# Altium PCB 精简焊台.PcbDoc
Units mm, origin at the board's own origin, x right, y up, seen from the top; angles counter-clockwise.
Board outline 70 x 50.01 mm, 2 copper layers (Top Layer, Bottom Layer), stack 0.325 mm thick; 94 components, 71 nets, 283 pads, 209 vias.
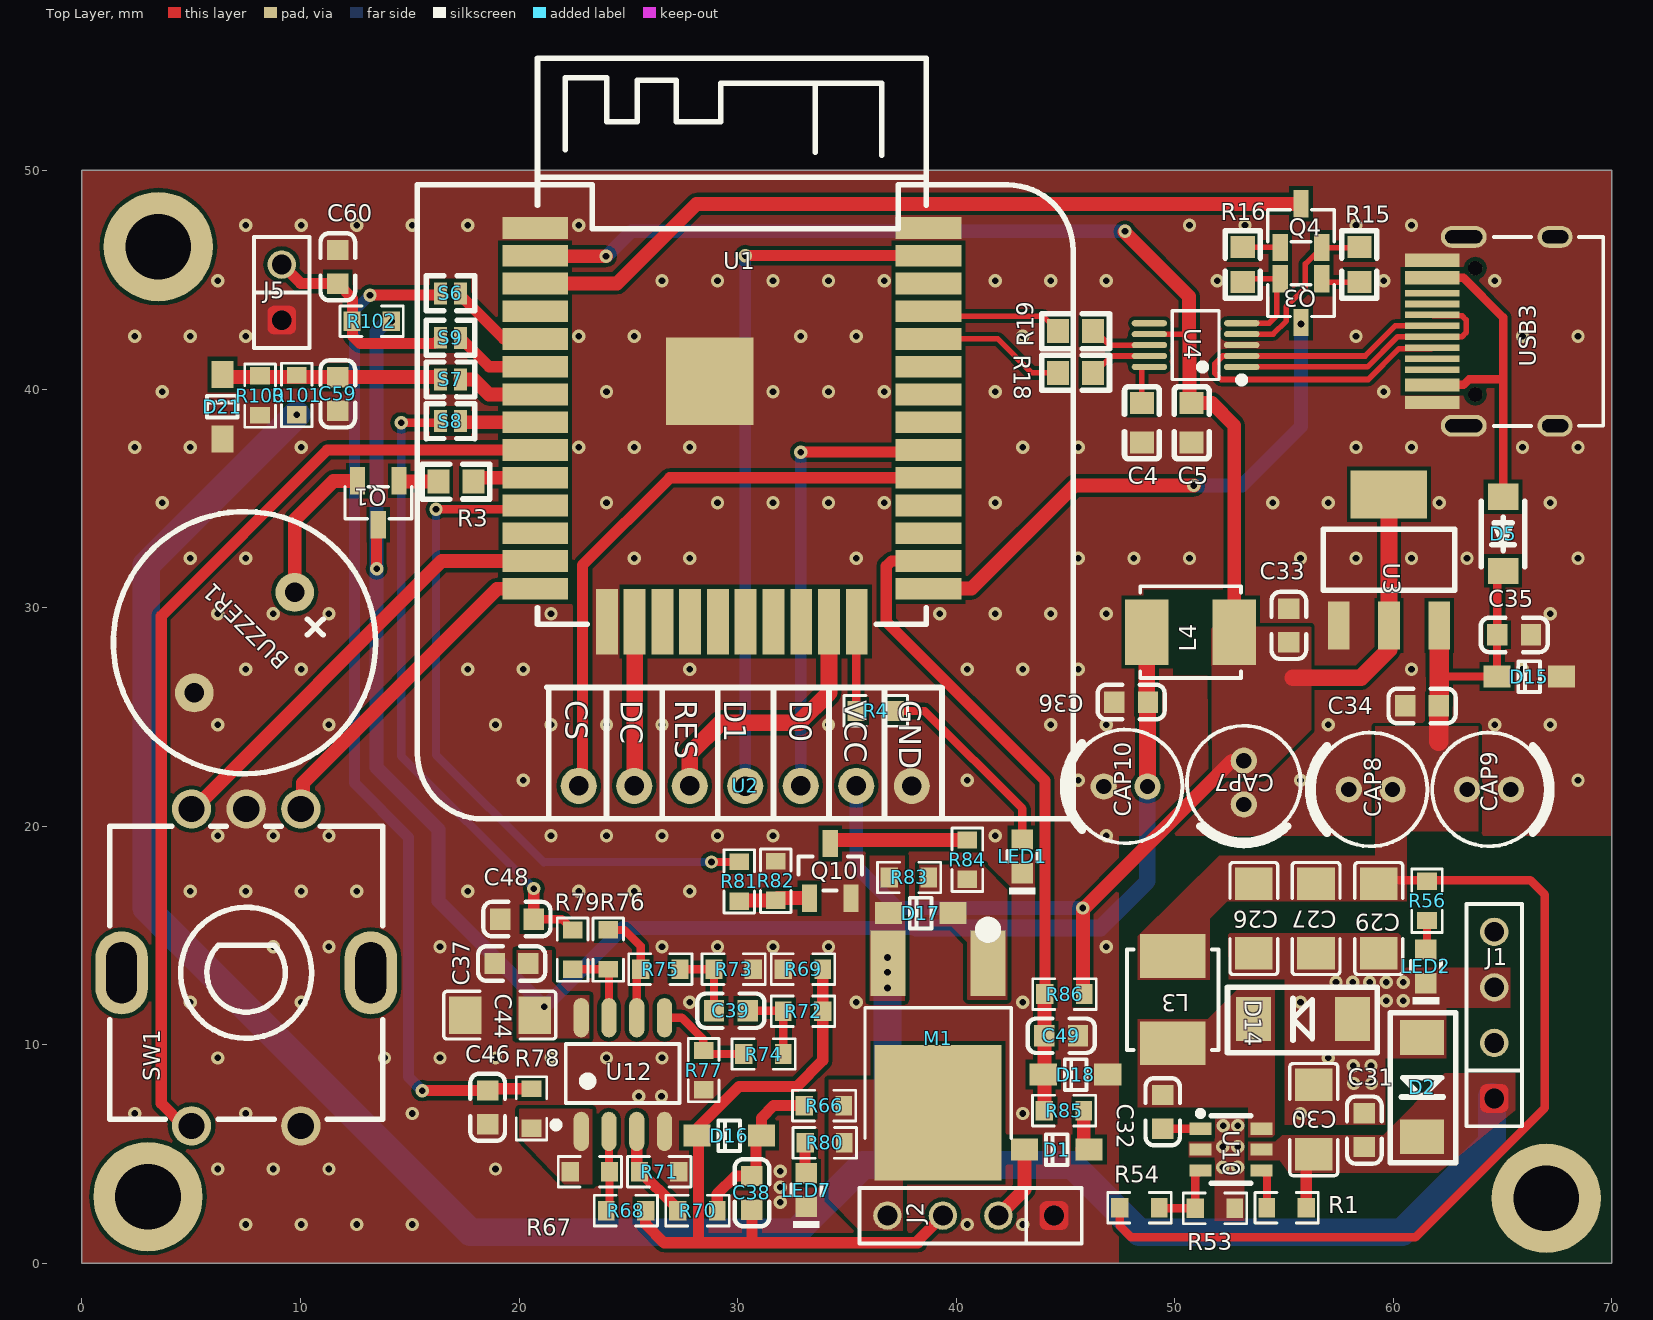
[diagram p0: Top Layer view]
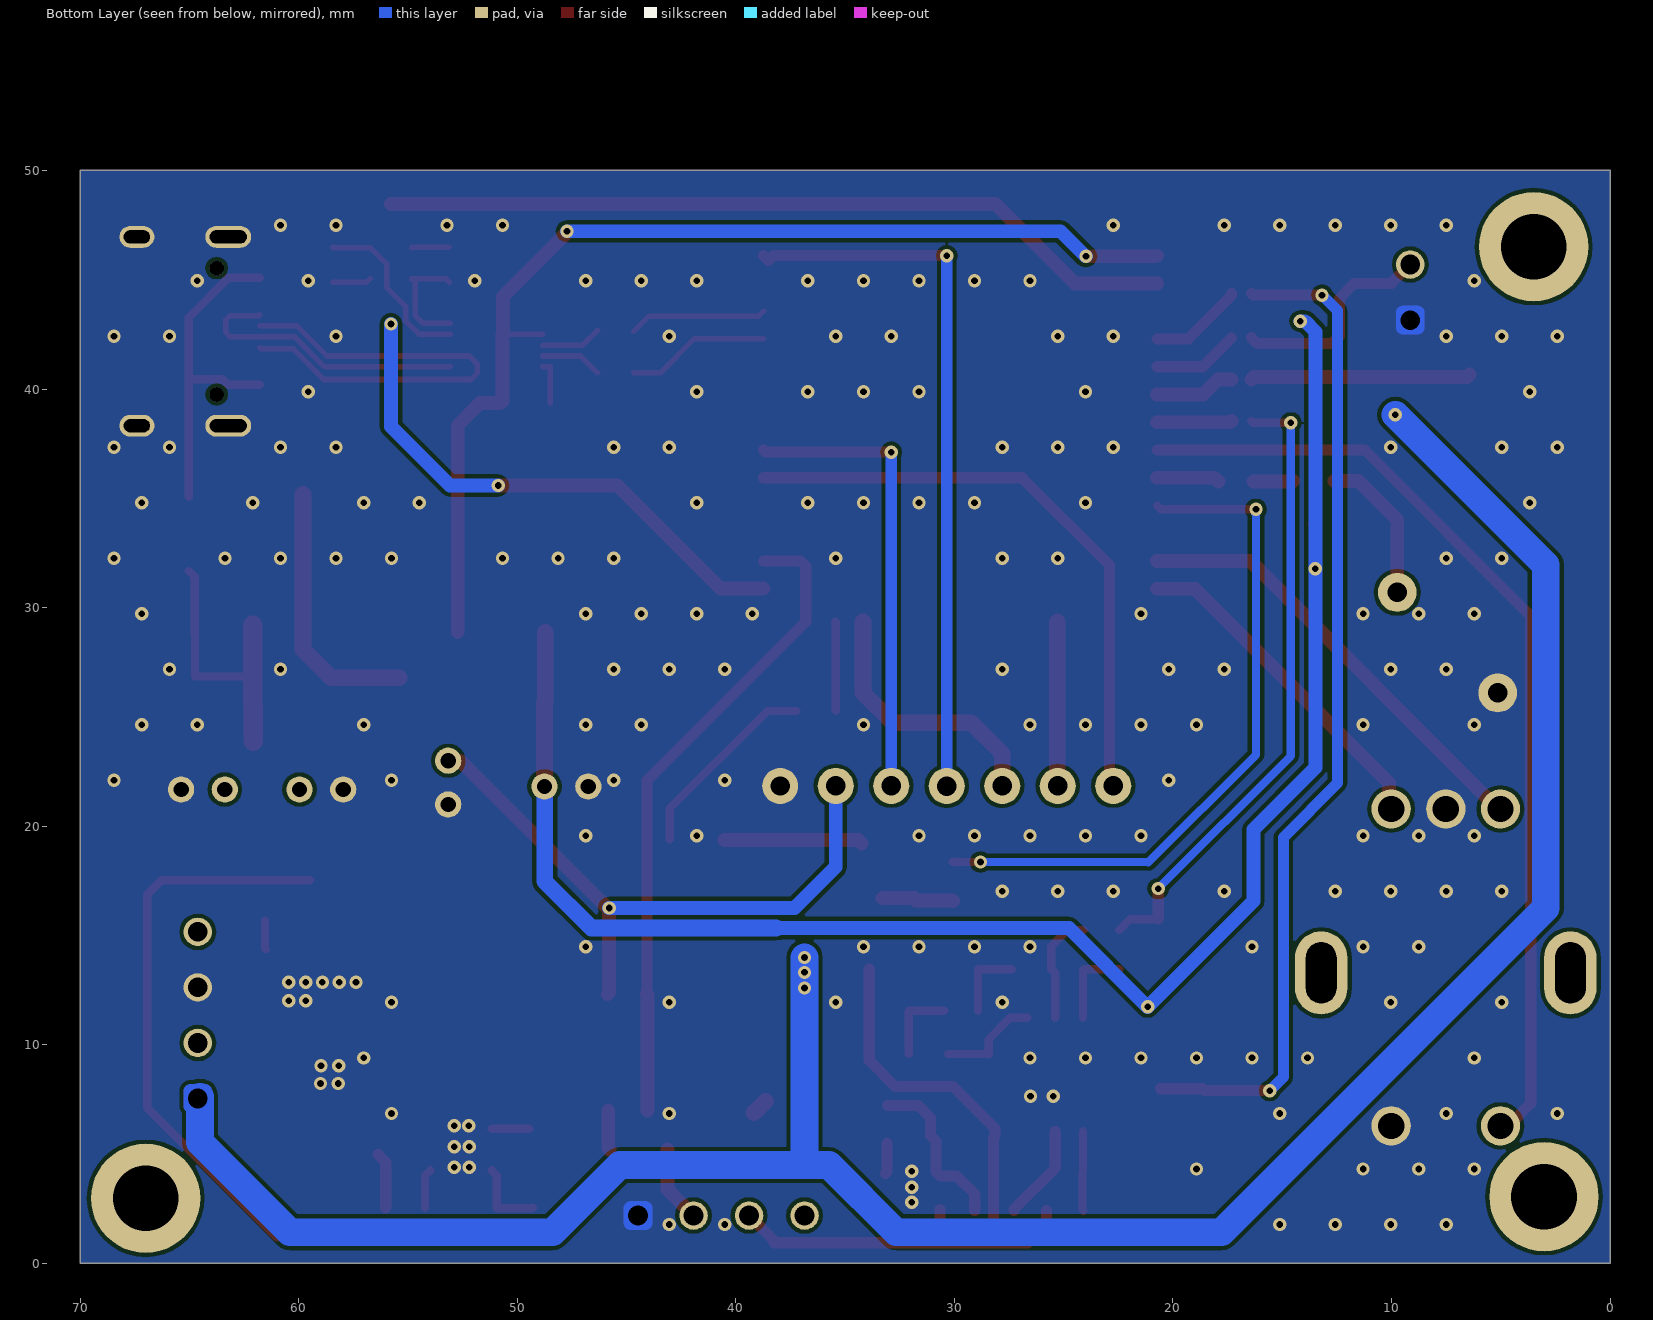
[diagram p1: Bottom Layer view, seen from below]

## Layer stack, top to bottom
Top Solder: solder mask 0.0102, Solder Resist, Dk 3.5
Top Layer: signal copper 0.0356
Dielectric 1: core 0.254, FR-4, Dk 4.2
Bottom Layer: signal copper 0.0356
Bottom Solder: solder mask 0.0102, Solder Resist, Dk 3.5

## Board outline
0,0 0,50.013 70.002,50.013 70.002,0

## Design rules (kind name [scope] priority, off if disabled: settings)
Clearance [All] p1: gap=0.178 ignorepadtopadclearanceinfootprint=FALSE
PolygonConnect PolygonConnect_2 [All] p1: connectstyle=Direct reliefconductorwidth=0.254 reliefentries=4 polygonreliefangle="90 Angle" airgapwidth=0.254
PolygonConnect PolygonConnect_1 [IsVia] p2: connectstyle=Direct reliefconductorwidth=0.254 reliefentries=4 polygonreliefangle="90 Angle" airgapwidth=0.254
PolygonConnect [All] p3: connectstyle=Relief reliefconductorwidth=0.254 reliefentries=4 polygonreliefangle="90 Angle" airgapwidth=0.254
RoutingVias [All] p1: holewidth=0.711 width=1.27 viastyle="Through Hole" minholewidth=0.711 minwidth=1.27 maxholewidth=0.711 maxwidth=1.27
SolderMaskExpansion [All] p1: expansion=0.064
Width Width_1 [InNetClass('New Class')] p1: maxlimit=2.54 minlimit=0.254 preferedwidth=0.508
Width [All] p2: maxlimit=2.54 minlimit=0.254 preferedwidth=0.254
30 further rules are at their usual default settings.

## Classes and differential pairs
net class "New Class": 5V AVCC DVCC NetD17_1 NetJ2_4 VBUS VIN

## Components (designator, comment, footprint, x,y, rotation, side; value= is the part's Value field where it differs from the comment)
BUZZER1 "GMC1205YA-16R2048" BUZ-TH_BD12.0-P6.50-D0.6-FD 7.442,28.397 r45 top
C4 "1u" C0603 48.501,38.456 r270 top
C5 "10u" C0603 50.775,38.456 r90 top
C26 "10uF" 电容 53.848,15.875 r270 top
C27 "10uF" 电容 56.694,15.875 r270 top
C29 "0.1uF" 电容 59.563,15.875 r270 top
C30 "4.7uF" 电容 56.134,6.477 r90 top
C31 "0.1uF" 0603C 58.674,6.096 r90 top
C32 "0.1uF" 0603C 49.454,6.934 r270 top
C33 "0.1uF" 0603C 55.22,29.185 r270 top
C34 "0.1uF" 0603C 61.316,25.502 r0 top
C35 "0.1uF" 0603C 65.532,28.753 r0 top
C36 "0.1uF" 0603C 48.006,25.679 r0 top
C37 "0.1uF" 0603C 19.66,13.716 r0 top
C38 "0.1uF" 0603C 30.658,3.226 r270 top
C39 "0.1uF" 0603C 29.693,11.557 r180 top
C44 "4.7uF" 电容 19.025,11.582 r0 top
C46 "10nF" 0603C 18.567,7.137 r270 top
C48 "10nF" 0603C 19.906,15.748 r180 top
C49 "0.1uF" 0603C 44.806,10.414 r180 top
C59 "1uF" 0603C 11.709,39.776 r270 top
C60 "1uF" 0603C 11.709,45.593 r90 top
CAP7 "22uF" CAPX-5.0 53.162,21.996 r90 top
CAP8 "22uF" CAPX-5.0 58.963,21.679 r0 top
CAP9 "100uF" CAPX-5.0 64.38,21.679 r180 top
CAP10 "22uF" CAPX-5.0 47.752,21.819 r0 top
D1 "1N4148" LC-SOD-123 44.602,5.207 r0 top
D2 "TVS" "二极管 SMA(DO-214AC)" 61.316,10.123 r270 top
D5 "1N5819HW-7-F" SOD-123_L2.8-W1.8-LS3.7-FD 65.024,33.376 r270 top
D14 "B5819" "二极管 SMA(DO-214AC)" 57.926,11.176 r180 top
D15 "SMA6.0A" LC-SOD-123 66.218,26.848 r0 top
D16 "1N4148" LC-SOD-123 29.616,5.842 r0 top
D17 "ZMM12" LC-SOD-123 38.379,16.027 r0 top
D18 "SMF3.3A" LC-SOD-123 45.466,8.636 r0 top
D21 "SMF3.3A" LC-SOD-123 6.426,39.192 r270 top
J1 "CONN4" SIP-4 64.618,7.544 r90 top
J2 "CONN4" SIP-4 44.475,2.184 r180 top
J5 "NTC 10K" SIP-2 9.144,43.155 r90 top
L3 "22uH" LIN0520 49.911,12.065 r90 top
L4 "22uH" LIN0520 50.724,28.88 r180 top
LED1 "LED" LC-0603-LED 43.028,18.618 r270 top
LED2 "LED" LC-0603-LED 61.493,13.589 r270 top
LED7 "LED" LC-0603-LED 33.147,3.353 r270 top
M1 "MOS-ASM6115" MOS-ASM6115 39.802,9.5 r90 top
Q1 "S8050" SOT-23-3_L2.9-W1.3-P1.90-LS2.4-BR 13.564,34.798 r90 top
Q3 "S8050" SOT-23-3_L2.9-W1.3-P1.90-LS2.4-BR 55.778,44.044 r90 top
Q4 "S8050" SOT-23-3_L2.9-W1.3-P1.90-LS2.4-BR 55.778,47.473 r270 top
Q10 "S8050" LC-SOT-23(SOT-23-3) 34.239,17.958 r270 top
R1 "100K" 0603R 55.118,2.54 r0 top
R3 "10k" R0603 17.12,35.763 r0 top
R4 "2K" 0603R 36.322,25.273 r180 top
R15 "10k" R0603 58.445,45.695 r90 top
R16 "10k" R0603 53.111,45.695 r270 top
R18 "220R" R0603 45.466,40.742 r180 top
R19 "220R" R0603 45.466,42.647 r180 top
R53 "18K" 0603R 51.841,2.515 r180 top
R54 "100K" 0603R 48.387,2.54 r180 top
R56 "3K" 0603R 61.544,16.586 r90 top
R66 "10K" 0603R 33.96,7.214 r180 top
R67 "200K" 0603R 23.241,4.191 r180 top
R68 "2K" 0603R 24.892,2.413 r0 top
R69 "0.02R" 0603R 32.995,13.462 r180 top
R70 "2K" 0603R 28.169,2.413 r180 top
R71 "200K" 0603R 26.416,4.191 r0 top
R72 "10R" 0603R 32.995,11.532 r0 top
R73 "10R" 0603R 29.82,13.462 r0 top
R74 "1K" 0603R 31.191,9.576 r180 top
R75 "1K" 0603R 26.467,13.462 r180 top
R76 "20K" 0603R 24.079,14.351 r90 top
R77 "20K" 0603R 28.448,8.839 r270 top
R78 "1K" 0603R 20.574,7.087 r270 top
R79 "10K" 0603R 22.454,14.351 r270 top
R80 "10K" 0603R 33.985,5.512 r180 top
R81 "1K" 0603R 30.074,17.475 r270 top
R82 "51K" 0603R 31.75,17.501 r270 top
R83 "10K" 0603R 37.846,17.653 r180 top
R84 "2K" 0603R 40.513,18.466 r270 top
R85 "1K" 0603R 44.938,6.985 r180 top
R86 "10K" 0603R 44.958,12.319 r180 top
R100 "1K" 0603R 8.153,39.7 r90 top
R101 "10K" 0603R 9.83,39.726 r270 top
R102 "10K" 0603R 13.259,43.104 r0 top
S6 "Solder" SW_HAND_WELD_JX 16.866,44.374 r180 top
S7 "Solder" SW_HAND_WELD_JX 16.866,40.437 r180 top
S8 "Solder" SW_HAND_WELD_JX 16.866,38.534 r180 top
S9 "Solder" SW_HAND_WELD_JX 16.866,42.342 r180 top
SW1 "Rotary Enc" SW-TH_PEC11R-4XXXF-SXXXX 7.518,13.538 r0 top
U1 "ESP32-S" WIRELM-SMD_ESP32-S 29.735,38.366 r0 top
U2 "0.96OLED" "OLED 12864 SPI 7P" 30.352,21.84 r0 top
U3 "AMS1117" "LDO线性稳压 (SOT-223)" 59.803,32.185 r270 top
U4 "CH340E" MSOP-10_L3.0-W3.0-P0.50-LS5.0-BL 50.952,42.012 r90 top
U10 "LMR16006" "开关电源 (LMR16006)" 52.959,5.334 r270 top
U12 "GS8552" LC-SOP-8-150MIL 24.74,8.636 r0 top
USB3 "USB-TYPEC-16P" USB-TYPE-C-16P 67.404,38.321 r90 top

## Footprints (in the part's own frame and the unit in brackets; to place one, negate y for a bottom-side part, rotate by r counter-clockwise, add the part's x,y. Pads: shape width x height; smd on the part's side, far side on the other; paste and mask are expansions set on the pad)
0603C [mm]
  rect 0.93x0.98 smd: 1(-0.77,0) 2(0.77,0)
  silkscreen extent -1.53,-0.79 1.54,0.79, body extent -0.8,-0.4 0.8,0.4, height 0.3
0603R [mm]
  rect 0.762x0.9 smd: 1(-0.9,0)
  rect 0.8x0.9 smd: 2(0.9,0)
  silkscreen extent -1.45,-0.7 1.45,0.7, body extent -0.85,-0.4 0.85,0.4, height 0.56
BUZ-TH_BD12.0-P6.50-D0.6-FD [mil]
  round 70 hole 35.4: 1(128,0) 2(-128,0)
  silkscreen extent -236,-236 236,236
C0603 [mm]
  rect 1x1.1 smd: 1(-0.9,0) 2(0.9,0)
  silkscreen extent -1.65,-0.8 1.65,0.8
CAPX-5.0 [mm]
  round 1.2 hole 0.7: 1(1,0) 2(-1,0)
  silkscreen extent -2.83,-2.6 2.6,2.6
LC-0603-LED [mm]
  rect 0.93x0.98 smd: A(-0.77,0) K(0.77,0)
  silkscreen extent -0.25,-0.69 1.72,0.69
LC-SOD-123 [mm]
  rect 1.25x1 smd: 1(1.475,0) 2(-1.475,0)
  silkscreen extent -0.5,-0.7 0.5,0.7
LC-SOP-8-150MIL [mm]
  oval 0.7x1.8 smd: 1(-1.893,-2.6) 2(-0.623,-2.6) 3(0.647,-2.6) 4(1.917,-2.6) 5(1.917,2.6) 6(0.647,2.6) 7(-0.623,2.6) 8(-1.893,2.6)
  silkscreen extent -3.2,-2.45 2.6,1.4
LC-SOT-23(SOT-23-3) [mm]
  rect 1.25x0.7 smd: 1(1.25,-0.95) 2(1.25,0.95) 3(-1.25,0)
  silkscreen extent -0.65,-1.46 0.9,1.46
"LDO线性稳压 (SOT-223)" [mm]
  rect 2.2x1 smd: 1(3,-2.3) 2(3,0) 3(3,2.3)
  rect 2.2x3.5 smd: 2(-3,0)
  silkscreen extent -1.4,-3 1.4,3, body extent -3.49,-3.24 3.49,3.24, height 1.64
LIN0520 [mm]
  rect 2x3 smd: 1(-2,0) 2(2,0)
  silkscreen extent -2.3,-2.1 2.3,2.1
MOS-ASM6115 [mm]
  rect 3x1.6 smd: 1(4.233,-1.662) 3(4.233,2.918)
  rect 6.2x5.8 smd: 2(-2.615,0.628)
  silkscreen extent -3.78,-2.72 6.06,3.97
MSOP-10_L3.0-W3.0-P0.50-LS5.0-BL [mm]
  oval 0.28x1.62 smd: 1(-1,-2.11) 2(-0.5,-2.11) 3(0,-2.11) 4(0.5,-2.11) 5(1,-2.11) 6(1,2.11) 7(0.5,2.11) 8(0,2.11) 9(-0.5,2.11) 10(-1,2.11)
  silkscreen extent -1.74,-2.26 1.58,1.07
"OLED 12864 SPI 7P" [mm]
  round 1.65 hole 0.89: 1(7.619,-0.001) 2(5.079,0.004) 3(2.539,0.004) 4(-0.001,-0.004) 5(-2.539,0.001) 6(-5.079,0.001) 7(-7.619,0.004)
  silkscreen extent -15,-1.5 15,27.5
R0603 [mm]
  rect 1x1.1 smd: 1(-0.8,0) 2(0.8,0)
  silkscreen extent -1.55,-0.8 1.55,0.81
SIP-2 [mm]
  round 0 hole 0.9: 1(0,0)
  round 1.3 hole 0.9: 2(2.54,0)
  Top Layer region: -0.65,0.325 -0.649,0.349 -0.646,0.373 -0.642,0.397 -0.636,0.421 -0.628,0.444 -0.618,0.466 -0.606,0.488 -0.594,0.508 -0.579,0.528 -0.563,0.546 -0.546,0.563 -0.528,0.579 -0.508,0.594 -0.488,0.606 -0.466,0.618 -0.444,0.628 -0.421,0.636 -0.397,0.642 -0.373,0.646 -0.349,0.649 -0.325,0.65 0.325,0.65 0.349,0.649 0.373,0.646 0.397,0.642 0.421,0.636 0.444,0.628 0.466,0.618 0.488,0.606 0.508,0.594 0.528,0.579 0.546,0.563 0.563,0.546 0.579,0.528 0.594,0.508 0.606,0.488 0.618,0.466 0.628,0.444 0.636,0.421 0.642,0.397 0.646,0.373 0.649,0.349 0.65,0.325 0.65,-0.325 0.649,-0.349 0.646,-0.373 0.642,-0.397 0.636,-0.421 0.628,-0.444 0.618,-0.466 0.606,-0.488 0.594,-0.508 0.579,-0.528 0.563,-0.546 0.546,-0.563 0.528,-0.579 0.508,-0.594 0.488,-0.606 0.466,-0.618 0.444,-0.628 0.421,-0.636 0.397,-0.642 0.373,-0.646 0.349,-0.649 0.325,-0.65 -0.325,-0.65 -0.349,-0.649 -0.373,-0.646 -0.397,-0.642 -0.421,-0.636 -0.444,-0.628 -0.466,-0.618 -0.488,-0.606 -0.508,-0.594 -0.528,-0.579 -0.546,-0.563 -0.563,-0.546 -0.579,-0.528 -0.594,-0.508 -0.606,-0.488 -0.618,-0.466 -0.628,-0.444 -0.636,-0.421 -0.642,-0.397 -0.646,-0.373 -0.649,-0.349 -0.65,-0.325
  Bottom Layer region: -0.65,0.325 -0.649,0.349 -0.646,0.373 -0.642,0.397 -0.636,0.421 -0.628,0.444 -0.618,0.466 -0.606,0.488 -0.594,0.508 -0.579,0.528 -0.563,0.546 -0.546,0.563 -0.528,0.579 -0.508,0.594 -0.488,0.606 -0.466,0.618 -0.444,0.628 -0.421,0.636 -0.397,0.642 -0.373,0.646 -0.349,0.649 -0.325,0.65 0.325,0.65 0.349,0.649 0.373,0.646 0.397,0.642 0.421,0.636 0.444,0.628 0.466,0.618 0.488,0.606 0.508,0.594 0.528,0.579 0.546,0.563 0.563,0.546 0.579,0.528 0.594,0.508 0.606,0.488 0.618,0.466 0.628,0.444 0.636,0.421 0.642,0.397 0.646,0.373 0.649,0.349 0.65,0.325 0.65,-0.325 0.649,-0.349 0.646,-0.373 0.642,-0.397 0.636,-0.421 0.628,-0.444 0.618,-0.466 0.606,-0.488 0.594,-0.508 0.579,-0.528 0.563,-0.546 0.546,-0.563 0.528,-0.579 0.508,-0.594 0.488,-0.606 0.466,-0.618 0.444,-0.628 0.421,-0.636 0.397,-0.642 0.373,-0.646 0.349,-0.649 0.325,-0.65 -0.325,-0.65 -0.349,-0.649 -0.373,-0.646 -0.397,-0.642 -0.421,-0.636 -0.444,-0.628 -0.466,-0.618 -0.488,-0.606 -0.508,-0.594 -0.528,-0.579 -0.546,-0.563 -0.563,-0.546 -0.579,-0.528 -0.594,-0.508 -0.606,-0.488 -0.618,-0.466 -0.628,-0.444 -0.636,-0.421 -0.642,-0.397 -0.646,-0.373 -0.649,-0.349 -0.65,-0.325
  silkscreen extent -1.27,-1.27 3.81,1.27
SIP-4 [mm]
  round 0 hole 0.9: 1(0,0)
  round 1.3 hole 0.9: 2(2.54,0) 3(5.08,0) 4(7.62,0)
  Top Layer region: -0.65,0.325 -0.649,0.349 -0.646,0.373 -0.642,0.397 -0.636,0.421 -0.628,0.444 -0.618,0.466 -0.606,0.488 -0.594,0.508 -0.579,0.528 -0.563,0.546 -0.546,0.563 -0.528,0.579 -0.508,0.594 -0.488,0.606 -0.466,0.618 -0.444,0.628 -0.421,0.636 -0.397,0.642 -0.373,0.646 -0.349,0.649 -0.325,0.65 0.325,0.65 0.349,0.649 0.373,0.646 0.397,0.642 0.421,0.636 0.444,0.628 0.466,0.618 0.488,0.606 0.508,0.594 0.528,0.579 0.546,0.563 0.563,0.546 0.579,0.528 0.594,0.508 0.606,0.488 0.618,0.466 0.628,0.444 0.636,0.421 0.642,0.397 0.646,0.373 0.649,0.349 0.65,0.325 0.65,-0.325 0.649,-0.349 0.646,-0.373 0.642,-0.397 0.636,-0.421 0.628,-0.444 0.618,-0.466 0.606,-0.488 0.594,-0.508 0.579,-0.528 0.563,-0.546 0.546,-0.563 0.528,-0.579 0.508,-0.594 0.488,-0.606 0.466,-0.618 0.444,-0.628 0.421,-0.636 0.397,-0.642 0.373,-0.646 0.349,-0.649 0.325,-0.65 -0.325,-0.65 -0.349,-0.649 -0.373,-0.646 -0.397,-0.642 -0.421,-0.636 -0.444,-0.628 -0.466,-0.618 -0.488,-0.606 -0.508,-0.594 -0.528,-0.579 -0.546,-0.563 -0.563,-0.546 -0.579,-0.528 -0.594,-0.508 -0.606,-0.488 -0.618,-0.466 -0.628,-0.444 -0.636,-0.421 -0.642,-0.397 -0.646,-0.373 -0.649,-0.349 -0.65,-0.325
  Bottom Layer region: -0.65,0.325 -0.649,0.349 -0.646,0.373 -0.642,0.397 -0.636,0.421 -0.628,0.444 -0.618,0.466 -0.606,0.488 -0.594,0.508 -0.579,0.528 -0.563,0.546 -0.546,0.563 -0.528,0.579 -0.508,0.594 -0.488,0.606 -0.466,0.618 -0.444,0.628 -0.421,0.636 -0.397,0.642 -0.373,0.646 -0.349,0.649 -0.325,0.65 0.325,0.65 0.349,0.649 0.373,0.646 0.397,0.642 0.421,0.636 0.444,0.628 0.466,0.618 0.488,0.606 0.508,0.594 0.528,0.579 0.546,0.563 0.563,0.546 0.579,0.528 0.594,0.508 0.606,0.488 0.618,0.466 0.628,0.444 0.636,0.421 0.642,0.397 0.646,0.373 0.649,0.349 0.65,0.325 0.65,-0.325 0.649,-0.349 0.646,-0.373 0.642,-0.397 0.636,-0.421 0.628,-0.444 0.618,-0.466 0.606,-0.488 0.594,-0.508 0.579,-0.528 0.563,-0.546 0.546,-0.563 0.528,-0.579 0.508,-0.594 0.488,-0.606 0.466,-0.618 0.444,-0.628 0.421,-0.636 0.397,-0.642 0.373,-0.646 0.349,-0.649 0.325,-0.65 -0.325,-0.65 -0.349,-0.649 -0.373,-0.646 -0.397,-0.642 -0.421,-0.636 -0.444,-0.628 -0.466,-0.618 -0.488,-0.606 -0.508,-0.594 -0.528,-0.579 -0.546,-0.563 -0.563,-0.546 -0.579,-0.528 -0.594,-0.508 -0.606,-0.488 -0.618,-0.466 -0.628,-0.444 -0.636,-0.421 -0.642,-0.397 -0.646,-0.373 -0.649,-0.349 -0.65,-0.325
  silkscreen extent -1.27,-1.27 8.89,1.27
SOD-123_L2.8-W1.8-LS3.7-FD [mm]
  rect 1.2x1.4 smd: 1(-1.7,0) 2(1.7,0)
  silkscreen extent -1.5,-1 1.5,1
SOT-23-3_L2.9-W1.3-P1.90-LS2.4-BR [mm]
  rect 1.25x0.7 smd: 1(1,-0.95) 2(1,0.95) 3(-1,0)
  silkscreen extent -0.73,-1.53 0.73,1.53
SW-TH_PEC11R-4XXXF-SXXXX [mm]
  round 1.8 hole 1.2: 1(2.5,-7.25) 2(-2.5,-7.25) A(2.5,7.25) B(-2.5,7.25) C(0,7.25)
  oval 2.4x3.8 hole 1.4 slot 2.8 at 90 deg: MT1(5.7,-0.25) MT2(-5.7,-0.25)
  silkscreen extent -6.25,-6.95 6.25,6.45
SW_HAND_WELD_JX [mm]
  rect 0.6x1 smd: 1(-0.45,0.002) 2(0.45,-0.003)
  silkscreen extent -1.1,-0.8 1.1,0.8
USB-TYPE-C-16P [mm]
  oval 1x2.1 hole 0.6 slot 1.7 at 90 deg: 0(0,4.18) 0(8.64,4.18)
  oval 1x1.6 hole 0.6 slot 1.2 at 90 deg: 0(0,0) 0(8.64,0)
  rect 0.6x2.5 smd: A1(1.07,5.625) A4(1.87,5.625) A9(6.77,5.625) A12(7.57,5.625)
  rect 0.3x2.5 smd: A5(3.07,5.625) A6(4.07,5.625) A7(4.57,5.625) A8(5.57,5.625) B5(6.07,5.625) B6(5.07,5.625) B7(3.57,5.625) B8(2.57,5.625)
  round 0.65 hole 0.65 slot 0.655 at 90 deg: G(1.43,3.65) G(7.21,3.65)
  silkscreen extent -0.01,-2.2 8.64,2.79
WIRELM-SMD_ESP32-S [mm]
  rect 3x1 smd: 1(-9,9.005) 2(-9,7.735) 3(-9,6.465) 4(-9,5.195) 5(-9,3.925) 6(-9,2.655) 7(-9,1.385) 8(-9,0.115) 9(-9,-1.155) 10(-9,-2.425) 11(-9,-3.695) 12(-9,-4.965) 13(-9,-6.235) 14(-9,-7.505) 25(9,-7.505) 26(9,-6.235) 27(9,-4.965) 28(9,-3.695) 29(9,-2.425) 30(9,-1.155) 31(9,0.115) 32(9,1.385) 33(9,2.655) 34(9,3.925) 35(9,5.195) 36(9,6.465) 37(9,7.735) 38(9,9.005)
  rect 1x3 smd: 15(-5.715,-9.005) 16(-4.445,-9.005) 17(-3.175,-9.005) 18(-1.905,-9.005) 19(-0.635,-9.005) 20(0.635,-9.005) 21(1.905,-9.005) 22(3.175,-9.005) 23(4.445,-9.005) 24(5.715,-9.005)
  rect 4x4 smd: 39(-1,1.995)
  silkscreen extent -8.89,-9.13 8.89,16.78
"二极管 SMA(DO-214AC)" [mil]
  rect 63x78.74 smd: 1(-8,0) 2(170.56,0)
  silkscreen extent -53,-57 217,61, body extent -8,-52 174,54, height 94
"开关电源 (LMR16006)" [mm]
  rect 0.55x1 smd: 1(-0.823,-1.786) 2(0.127,-1.786) 3(1.077,-1.786) 4(1.077,1.014) 5(0.127,1.014) 6(-0.823,1.014)
  silkscreen extent -1.65,-1.91 1.68,0.51
电容 [mm] "1206"
  rect 1.485x1.728 smd: 1(-1.493,-0.228) 2(1.692,-0.228)
  silkscreen extent -2.46,-1.32 2.66,0.86

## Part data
BUZZER1: BOM_JLCPCB Part Class="Extended Part", BOM_Manufacturer=INGHAi
D2: library part B5819
D5: BOM_JLCPCB Part Class="Extended Part", BOM_Manufacturer=DIODES
Q1 Q3 Q4: BOM_JLCPCB Part Class="Extended Part", BOM_Manufacturer=WPMtek(维攀微)
R1 R53: library part 2K
R54: library part 10K
SW1: BOM_JLCPCB Part Class="Extended Part", BOM_Manufacturer=BOURNS, BOM_Manufacturer Part=PEC11R-4015F-S0024
U1: BOM_JLCPCB Part Class="Extended Part", BOM_Manufacturer=Ai-Thinker, Package Display=No
U3: "线性稳压3.3V-5V 1A"
U4: BOM_JLCPCB Part Class="Extended Part", BOM_Manufacturer=WCH
U10: library part HT7463B

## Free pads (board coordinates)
  round 5 hole 3 unplated: 8(3.5,46.513) 10(3.025,3.051) 10(67.002,2.975)

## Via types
v1: diameter 0.61, hole 0.305, Top Layer to Bottom Layer, 167 vias
v2: diameter 0.61/0.61 (per signal layer), hole 0.305, Top Layer to Bottom Layer, tented both sides, 42 vias

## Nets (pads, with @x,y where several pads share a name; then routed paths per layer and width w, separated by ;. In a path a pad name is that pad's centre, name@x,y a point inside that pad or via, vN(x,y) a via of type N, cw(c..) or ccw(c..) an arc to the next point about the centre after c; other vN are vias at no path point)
5V: C26.1 C27.1 C29.1 C34.2 C35.1 CAP8.1 CAP9.1 D5.2 D15.2 L3.2 R54.2 R56.2 U3.3 | length 53.3
  Top Layer w0.381: R54.2 47.487,1.713 48.006,1.194 61.011,1.194 66.929,7.112 66.929,16.866 66.269,17.526 C29.1@59.493,17.526 ; 62.111,26.848 D15.2 64.743,28.734 C35.1 64.762,31.414 D5.2
  Top Layer w0.889: 62.086,23.884 C34.2 62.111,25.527 62.111,26.848 62.103,26.856 U3.3
AVCC: C36.2 C37.2 C44.2 CAP10.1 L4.2 Q1.3 R102.2 U12.8 | length 78.4
  Top Layer w0.508: v2(13.487,31.775) 13.487,33.722 Q1.3
  Top Layer w0.762: L4.2 48.724,25.684 48.752,25.655 CAP10.1
  Bottom Layer w0.635: v2(14.173,43.104) 13.97,43.104 13.487,42.621 v2(13.487,31.775) 13.487,22.682 16.319,19.85 16.319,16.573 v2(21.158,11.735) 24.765,15.342 38.151,15.342
  Bottom Layer w0.762: 38.151,15.342 46.609,15.342 48.743,17.475 CAP10.1@48.743,21.819
DVCC: C5.2 C33.2 CAP7.1 L4.1 R86.1 U1.2 U2.2 U3.2 U4.7 | length 91.3
  Top Layer w0.254: U4.7 50.656,42.512 50.673,42.494
  Top Layer w0.635: U1.2 20.76,46.076 v2(23.978,46.076) ; R86.1 45.796,12.381 v2(45.796,16.256) 45.872,16.256 52.613,22.996 CAP7.1 ; v2(47.727,47.219) 47.701,47.193 50.656,44.239 50.656,42.512 ; 50.673,42.494 50.673,39.457 C5.2 51.703,39.356 52.724,38.335 L4.1
  Top Layer w0.762: 55.397,26.797 58.522,26.797 59.803,28.078 59.803,29.185 U3.2@59.803,35.185
  Bottom Layer w0.635: v2(23.978,46.076) 24.003,46.076 25.146,47.219 v2(47.727,47.219) ; U2.2 35.43,18.138 37.313,16.256 v2(45.796,16.256)
GND: BUZZER1.2 C4.2 C5.1 C26.2 C27.2 C29.2 C30.2 C31.2 C33.1 C34.1 C35.2 C36.1 C37.1 C44.1 C46.2 C48.2 C49.1 C59.2 C60.2 CAP7.2 CAP8.2 CAP9.2 CAP10.2 D2.1 D14.1 D15.1 D18.1 D21.1 J1.3 J2.1 J5.1 LED1.K LED2.K LED7.K Q10.2 R53.1 R69.2 R71.2 R73.2 R77.2 R82.1 R100.1 SW1.1 SW1.C U1.1 U1.15 U1.38 U1.39 U2.1 U3.1 U4.3 U10.2 U12.4 USB3.0 USB3.A1 USB3.A12
  other v1: 7.493,1.778 10.033,1.778 12.573,1.778 15.113,1.778 40.513,1.778 43.053,1.778 6.223,4.318 8.763,4.318 11.303,4.318 18.923,4.318 2.413,6.858 7.493,6.858 15.113,6.858 43.053,6.858 55.753,6.858 6.223,9.398 13.843,9.398 16.383,9.398 18.923,9.398 21.463,9.398 24.003,9.398 26.543,9.398 57.023,9.398 4.953,11.938 10.033,11.938 27.813,11.938 35.433,11.938 43.053,11.938 55.753,11.938 8.763,14.478 11.303,14.478 16.383,14.478 26.543,14.478 29.083,14.478 31.623,14.478 34.163,14.478 46.863,14.478 4.953,17.018 7.493,17.018 10.033,17.018 12.573,17.018 17.653,17.018 22.733,17.018 25.273,17.018 27.813,17.018 6.223,19.558 8.763,19.558 11.303,19.558 21.463,19.558 24.003,19.558 26.543,19.558 29.083,19.558 31.623,19.558 41.783,19.558 46.863,19.558 20.193,22.098 40.513,22.098 45.593,22.098 55.753,22.098 68.453,22.098 6.223,24.638 11.303,24.638 18.923,24.638 21.463,24.638 24.003,24.638 26.543,24.638 34.163,24.638 44.323,24.638 46.863,24.638 57.023,24.638 64.643,24.638 67.183,24.638 7.493,27.178 10.033,27.178 17.653,27.178 20.193,27.178 27.813,27.178 40.513,27.178 43.053,27.178 45.593,27.178 60.833,27.178 65.913,27.178 6.223,29.718 8.763,29.718 11.303,29.718 21.463,29.718 39.243,29.718 41.783,29.718 44.323,29.718 46.863,29.718 67.183,29.718 4.953,32.258 7.493,32.258 25.273,32.258 27.813,32.258 35.433,32.258 45.593,32.258 48.133,32.258 50.673,32.258 55.753,32.258 58.293,32.258 60.833,32.258 63.373,32.258 68.453,32.258 3.683,34.798 24.003,34.798 29.083,34.798 31.623,34.798 34.163,34.798 36.703,34.798 41.783,34.798 54.483,34.798 57.023,34.798 62.103,34.798 67.183,34.798 2.413,37.338 4.953,37.338 10.033,37.338 22.733,37.338 25.273,37.338 27.813,37.338 43.053,37.338 45.593,37.338 58.293,37.338 60.833,37.338 65.913,37.338 68.453,37.338 3.683,39.878 24.003,39.878 31.623,39.878 34.163,39.878 36.703,39.878 41.783,39.878 59.563,39.878 2.413,42.418 4.953,42.418 7.493,42.418 22.733,42.418 25.273,42.418 32.893,42.418 35.433,42.418 43.053,42.418 58.293,42.418 65.913,42.418 68.453,42.418 6.223,44.958 26.543,44.958 29.083,44.958 31.623,44.958 34.163,44.958 36.703,44.958 41.783,44.958 44.323,44.958 46.863,44.958 51.943,44.958 59.563,44.958 64.643,44.958 7.493,47.498 10.033,47.498 12.573,47.498 15.113,47.498 17.653,47.498 22.733,47.498 50.673,47.498 53.213,47.498 58.293,47.498 60.833,47.498
  other v2: 31.953,2.794 31.953,3.48 31.953,4.216 52.197,4.394 52.883,4.394 52.197,5.334 52.883,5.334 52.222,6.299 52.883,6.299 25.476,7.645 26.518,7.645 58.191,8.23 59.004,8.23 58.166,9.042 58.979,9.042 59.684,12.014 60.452,12.014 57.379,12.852 58.147,12.852 58.915,12.852 59.684,12.852 60.452,12.852
NetBUZZER1_1: BUZZER1.1 Q1.2 | length 6.9
  Top Layer w0.635: BUZZER1.1 9.741,34.024 11.516,35.798 Q1.2
NetC4_1: C4.1 U4.10 | length 2
  Top Layer w0.254: C4.1 48.501,41.012 U4.10
NetC32_1: C32.1 D14.2 L3.1 U10.6
NetC32_2: C32.2 U10.1 | length 1.7
  Top Layer w0.381: C32.2 51.166,6.164 U10.1
NetC38_1: C38.1 D16.1 R66.2 R70.1 | length 7.7
  Top Layer w0.508: R70.1 29.069,3.161 29.904,3.996 C38.1 30.836,4.174 30.836,5.586 D16.1 31.091,6.657 31.648,7.214 R66.2
NetC38_2: C38.2 D16.2 J2.3 R68.2 R69.1 R72.2 | length 33.1
  Top Layer w0.508: R68.2 25.792,1.792 26.645,0.94 28.143,0.94 ; C38.2 30.658,0.991 30.709,0.94 ; R69.1 33.895,9.282 32.708,8.095 30.065,8.095 28.141,6.172 D16.2 28.219,5.764 28.219,0.94 30.709,0.94 ; J2.3 38.252,1.041 38.252,0.94 30.709,0.94
NetC39_1: C39.1 R72.1 R74.1 | length 3.6
  Top Layer w0.381: C39.1 32.069,11.557 R72.1 32.095,9.579 R74.1
NetC39_2: C39.2 R73.1 R75.1 | length 3.5
  Top Layer w0.381: R75.1 R73.1 28.92,11.56 C39.2
NetC46_1: C46.1 R78.1 S6.2 | length 46.3
  Top Layer w0.508: v2(13.183,44.298) 16.337,44.298 S6.2 ; v2(15.57,7.899) 18.525,7.899 18.55,7.925 C46.1 18.647,7.987 R78.1
  Bottom Layer w0.508: v2(13.183,44.298) 12.471,43.586 12.471,21.971 14.952,19.491 14.952,8.518 v2(15.57,7.899)
NetC48_1: C48.1 R79.1 S8.2 | length 29.1
  Top Layer w0.381: v2(14.605,38.456) 16.334,38.456 S8.2 ; C48.1 21.957,15.748 R79.1
  Top Layer w0.508: C48.1 v2(20.676,17.145)
  Bottom Layer w0.381: v2(14.605,38.456) 14.605,23.216 v2(20.676,17.145)
NetC49_2: C49.2 D18.2 R85.2 R86.2 U1.26 | length 30
  Top Layer w0.508: U1.26 37.033,32.131 36.803,31.901 36.803,29.338 44.058,22.084 R86.2
  Top Layer w0.635: R85.2 44.038,12.299 R86.2
NetC59_1: C59.1 D21.2 R100.2 R101.1 S7.2 | length 10.1
  Top Layer w0.635: D21.2 6.547,40.546 C59.1 16.309,40.546 S7.2
NetC60_1: C60.1 J5.2 R102.1 S9.2 | length 9.9
  Top Layer w0.508: J5.2 10.016,44.823 C60.1 12.384,44.148 12.384,42.429 12.725,42.088 16.159,42.088 S9.2
NetD1_1: D1.1 R85.1 | length 1.8
  Top Layer w0.635: D1.1@45.773,5.207 45.838,5.272 R85.1
NetD1_2: D1.2 J2.2 | length 3.5
  Top Layer w0.635: J2.2 43.127,3.376 D1.2
NetD17_1: D17.1 M1.1 R83.1 R84.2
NetJ2_4: J2.4 M1.2 R66.1 R80.1 | length 0.8
  Top Layer w0.762: M1.2@38.641,7.417 M1.2
NetLED1_A: LED1.A R4.1 | length 9.1
  Top Layer w0.381: R4.1 38.557,25.273 43.028,20.803 LED1.A
NetLED2_A: LED2.A R56.1 | length 1.3
  Top Layer w0.381: LED2.A 61.544,14.41 R56.1
NetLED7_A: LED7.A R80.2 | length 1.4
  Top Layer w0.508: R80.2 33.085,4.185 LED7.A
NetQ1_1: Q1.1 R3.1 | length 1.8
  Top Layer w0.635: Q1.1 14.548,35.763 R3.1
NetQ3_1: Q3.1 R15.1 | length 1.8
  Top Layer w0.254: Q3.1 56.877,44.895 R15.1
NetQ3_2: Q3.2 R16.2 U4.5 | length 5.3
  Top Layer w0.254: U4.5 54.315,43.012 54.673,43.37 54.673,44.889 Q3.2 53.26,45.044 R16.2
NetQ3_3: Q3.3 U1.25 | length 24.8
  Top Layer w0.635: U1.25 38.747,30.873 40.703,30.873 45.415,35.585 v2(50.876,35.585)
  Bottom Layer w0.635: v2(50.876,35.585) 53.086,35.585 55.778,38.278 v2(55.778,42.977)
NetQ4_1: Q4.1 R16.1 | length 1.7
  Top Layer w0.254: R16.1 54.806,46.495 Q4.1
NetQ4_2: Q4.2 R15.2 U4.4 | length 8
  Top Layer w0.254: U4.4 54.5,42.512 55.105,43.116 55.105,43.777 55.982,44.653 55.982,45.726 Q4.2 58.423,46.473 R15.2
NetQ4_3: Q4.3 U1.3 | length 36.6
  Top Layer w0.635: U1.3 24.486,44.831 28.127,48.473 Q4.3
NetQ10_1: Q10.1 R81.2 R82.2 | length 3.3
  Top Layer w0.635: R81.2 30.099,16.601 R82.2 31.857,16.708 Q10.1
NetQ10_3: Q10.3 R84.1 | length 6.3
  Top Layer w0.635: Q10.3 34.397,19.366 R84.1
NetR1_1: R1.1 U10.4 | length 1.8
  Top Layer w0.381: U10.4 54.218,4.012 R1.1
NetR3_2: R3.2 U1.10 | length 2.9
  Top Layer w0.635: R3.2 18.097,35.941 U1.10
NetR4_2: R4.2 U1.24 | length 4.1
  Top Layer w0.381: R4.2 35.422,29.333 U1.24
NetR18_1: R18.1 U4.9 | length 2.8
  Top Layer w0.254: R18.1@46.33,40.741 47.1,41.512 U4.9
NetR18_2: R18.2 U1.34 | length 6.6
  Top Layer w0.254: U1.34 41.91,42.291 43.459,40.742 R18.2
NetR19_1: R19.1 U4.8 | length 2.8
  Top Layer w0.254: R19.1@46.33,42.685 47.003,42.012 U4.8
NetR19_2: R19.2 U1.35 | length 6.3
  Top Layer w0.254: U1.35 38.964,43.332 43.98,43.332 R19.2
NetR53_2: R53.2 R54.1 U10.3 | length 3.5
  Top Layer w0.381: R54.1 49.312,2.515 R53.2 50.941,4.025 U10.3
NetR67_1: R67.1 R68.1 U12.2 | length 3.7
  Top Layer w0.381: R68.1@24.094,2.413 24.141,2.46 R67.1 24.117,4.215 U12.2
NetR67_2: R67.2 R78.2 U12.1
NetR70_2: R70.2 R71.1 U12.3 | length 4.4
  Top Layer w0.508: U12.3 25.387,4.371 27.269,2.489 R70.2
NetR74_2: R74.2 R77.1 U12.5 | length 4.7
  Top Layer w0.381: U12.5 27.448,11.236 28.423,10.262 28.423,9.561 28.437,9.576 R74.2
NetR75_2: R75.2 R76.2 U12.6 | length 5.1
  Top Layer w0.381: R76.2 24.83,15.251 25.567,14.514 R75.2 25.387,13.282 U12.6
NetR76_1: R76.1 R79.2 U12.7 | length 3.9
  Top Layer w0.381: R79.2 R76.1 24.117,13.414 U12.7
NetR81_1: R81.1 U1.11 | length 31.8
  Top Layer w0.381: v2(16.205,34.493) 20.557,34.493 U1.11 ; v2(28.804,18.364) 30.012,18.364 30.037,18.339 R81.1
  Bottom Layer w0.381: v2(16.205,34.493) v2@16.205,34.341 ; v2@16.231,34.315 v2@16.205,34.341 ; v2(28.804,18.364) 21.158,18.364 21.133,18.339 16.205,23.266 v2@16.205,34.341
NetS6_1: S6.1 U1.5 | length 4.3
  Top Layer w0.508: S6.1 17.316,44.279 19.304,42.291 U1.5
NetS7_1: S7.1 U1.7 | length 3.7
  Top Layer w0.635: S7.1 17.935,40.435 18.618,39.751 U1.7
NetS8_1: S8.1 U1.8 | length 3.4
  Top Layer w0.635: S8.1 17.367,38.481 U1.8
NetS9_1: S9.1 U1.6 | length 4
  Top Layer w0.508: S9.1 18.634,41.021 U1.6
NetSW1_2: SW1.2 U1.9 | length 44.5
  Top Layer w0.508: SW1.2@5.12,6.288 4.659,6.288 3.632,7.315 3.632,29.616 11.227,37.211 U1.9
NetSW1_A: SW1.A U1.14 | length 15.5
  Top Layer w0.635: SW1.A@10.12,20.788 10.12,21.982 18.999,30.861 U1.14
NetSW1_B: SW1.B U1.13 | length 20.3
  Top Layer w0.635: SW1.B@5.12,20.788 16.463,32.131 U1.13
NetU1_12: U1.12
NetU1_16: U1.16 U2.6 | length 7.5
  Top Layer w0.762: U2.6@25.29,21.841 U1.16
NetU1_23: U1.23 U2.5 | length 12.3
  Top Layer w0.762: U2.5 27.813,23.317 29.235,24.74 32.817,24.74 34.18,26.103 U1.23
NetU1_27: U1.27
NetU1_28: U1.28
NetU1_29: U1.29 U2.7 | length 27.7
  Top Layer w0.508: U2.7 22.911,22.022 22.911,31.953 26.899,35.941 U1.29
NetU1_30: U1.30 U2.3 | length 21.2
  Top Layer w0.508: v2(32.89,37.112) 38.636,37.112 U1.30
  Bottom Layer w0.508: U2.3 v2(32.89,37.112)
NetU1_33: U1.33
NetU1_36: U1.36
NetU1_37: U1.37 U2.4 | length 32.8
  Top Layer w0.508: v2(30.35,46.104) 38.275,46.104 38.506,45.872 U1.37
  Bottom Layer w0.508: U2.4 v2(30.35,46.104)
NetU2_2: 
NetU4_1: U4.1 USB3.A6 USB3.B6 | length 13.2
  Top Layer w0.254: U4.1 58.818,41.012 60.198,42.391 USB3.A6 63.139,42.391 63.334,42.586 63.334,43.167 63.155,43.346 61.824,43.346 USB3.B6
NetU4_2: U4.2 USB3.A7 USB3.B7 | length 21.8
  Top Layer w0.254: USB3.B7 61.734,41.846 60.263,41.846 58.854,40.437 52.121,40.437 51.841,40.716 51.841,41.156 52.197,41.512 U4.2 58.707,41.512 60.087,42.891 USB3.A7
PGND: 
VBUS: D5.1 USB3.A4 USB3.A9 | length 15.5
  Top Layer w0.381: USB3.A4 63.211,40.191 63.464,40.444 65.024,40.444 ; USB3.A9 63.211,45.091 65.024,43.278 D5.1
VIN: C30.1 C31.1 D2.2 D17.2 J1.1 M1.3 R1.2 R83.2 R101.2 U10.5 | length 111.6
  Top Layer w0.508: R1.2 56.018,4.64 C30.1
  Bottom Layer w1.27: v2(9.83,38.826) 9.819,38.826 2.946,31.953 2.946,16.256 17.78,1.422 32.664,1.422 35.738,4.496 36.855,4.496 ; v2(36.855,13.995) v2(36.855,13.31) v2(36.855,12.598) 36.855,4.496 ; 64.516,7.62 64.516,5.537 60.401,1.422 48.387,1.422 45.314,4.496 36.855,4.496
pads on no net: J1.2 J1.4 SW1.MT1 SW1.MT2 U1.4 U1.17 U1.18 U1.19 U1.20 U1.21 U1.22 U1.31 U1.32 U4.6 USB3.A5 USB3.A8 USB3.B5 USB3.B8 USB3.G

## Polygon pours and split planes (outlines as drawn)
NetR67_2 on Top Layer "GND_L02_P-001" (solid, remove dead copper, pour order 12): 23.343,7.061 23.343,3.607 22.077,3.607 20.015,5.768 20.015,7.061
AVCC on Top Layer "GND_L02_P-001" (solid, remove dead copper, pour order 10): 21.488,14.326 21.488,12.903 22.123,12.268 23.216,12.268 23.216,10.287 22.936,10.287 19.888,10.287 19.888,14.326
NetJ2_4 on Top Layer "GND_L02_P-001" (solid, remove dead copper, pour order 20): 34.163,8.407 34.163,2.921 35.585,1.499 37.567,1.499 37.567,8.407
VIN on Top Layer "GND_L02_P-001" (solid, remove dead copper, pour order 22): 37.643,18.644 37.643,12.014 36.043,12.014 36.043,18.644
NetD17_1 on Top Layer "GND_L02_P-001" (solid, remove dead copper, pour order 28): 38.303,18.237 41.275,18.237 41.275,18.161 42.342,17.094 42.342,12.065 40.538,12.065 40.513,12.09 40.513,14.681 39.776,15.418 38.303,15.418
DVCC on Top Layer "GND_L02_P-001" (solid, remove dead copper, pour order 14): 51.664,29.134 56.21,29.134 56.236,29.108 56.236,24.409 54.051,22.225 51.714,22.225
GND on Top Layer "GND_L02_P-001" (solid, remove dead copper, pour order 38): 52.438,15.113 60.325,15.113 60.35,15.088 60.35,13.513 65.354,13.513 65.354,11.684 62.433,11.684 62.433,9.373 59.639,9.373 59.639,6.35 55.042,6.35 55.042,13.03 55.016,13.005 52.464,13.005
GND on Top Layer "GND_L02_P-001" (solid, remove dead copper, pour order 40): 50.648,5.563 51.841,5.563 51.841,6.629 53.188,6.629 53.188,1.956 51.841,1.956 51.841,4.851 50.648,4.851
5V on Top Layer "GND_L02_P-001" (solid, remove dead copper, pour order 4): 48.311,12.979 51.613,12.979 51.613,15.773 52.4,16.561 60.604,16.561 60.604,19.761 63.881,19.761 63.881,24.562 59.182,24.562 59.182,18.644 52.042,18.644 48.311,14.956
GND on Top Layer "GND_L02_P-001" (solid, remove dead copper, pour order 34): 47.447,0 47.447,19.558 70.002,19.558 70.002,50.013 0,50.013 0,0
VIN on Top Layer "GND_L02_P-001" (solid, remove dead copper, pour order 0): 65.583,7.004 65.583,8.687 62.357,8.687 59.538,5.867 54.915,5.867 54.61,5.563 53.365,5.563 53.365,4.724 54.813,4.724 55.222,4.14 62.058,4.14
NetC32_1 on Top Layer "GND_L02_P-001" (solid, remove dead copper, pour order 2): 53.365,5.766 54.559,5.766 54.585,5.74 54.585,12.497 52.832,12.497 51.511,11.176 48.311,11.176 48.311,7.366 48.311,7.137 53.365,7.137
GND on Bottom Layer "GND_L02_P-001" (solid, remove dead copper, pour order 32): 0,50.013 0,0 70.002,0 70.002,0.025 70.002,50.013

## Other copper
Top Layer:
  pour cut-out: 48.565,30.836 52.197,30.836 52.197,30.579 52.219,30.558 51.546,30.558 51.546,29.182 51.496,29.132 51.496,26.888 51.511,26.873 49.911,26.873 49.911,27.193 49.902,27.202 49.902,30.558 48.566,30.558 48.565,30.556

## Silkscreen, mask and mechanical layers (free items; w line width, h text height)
Mechanical 1:
  the board outline again, w0.254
